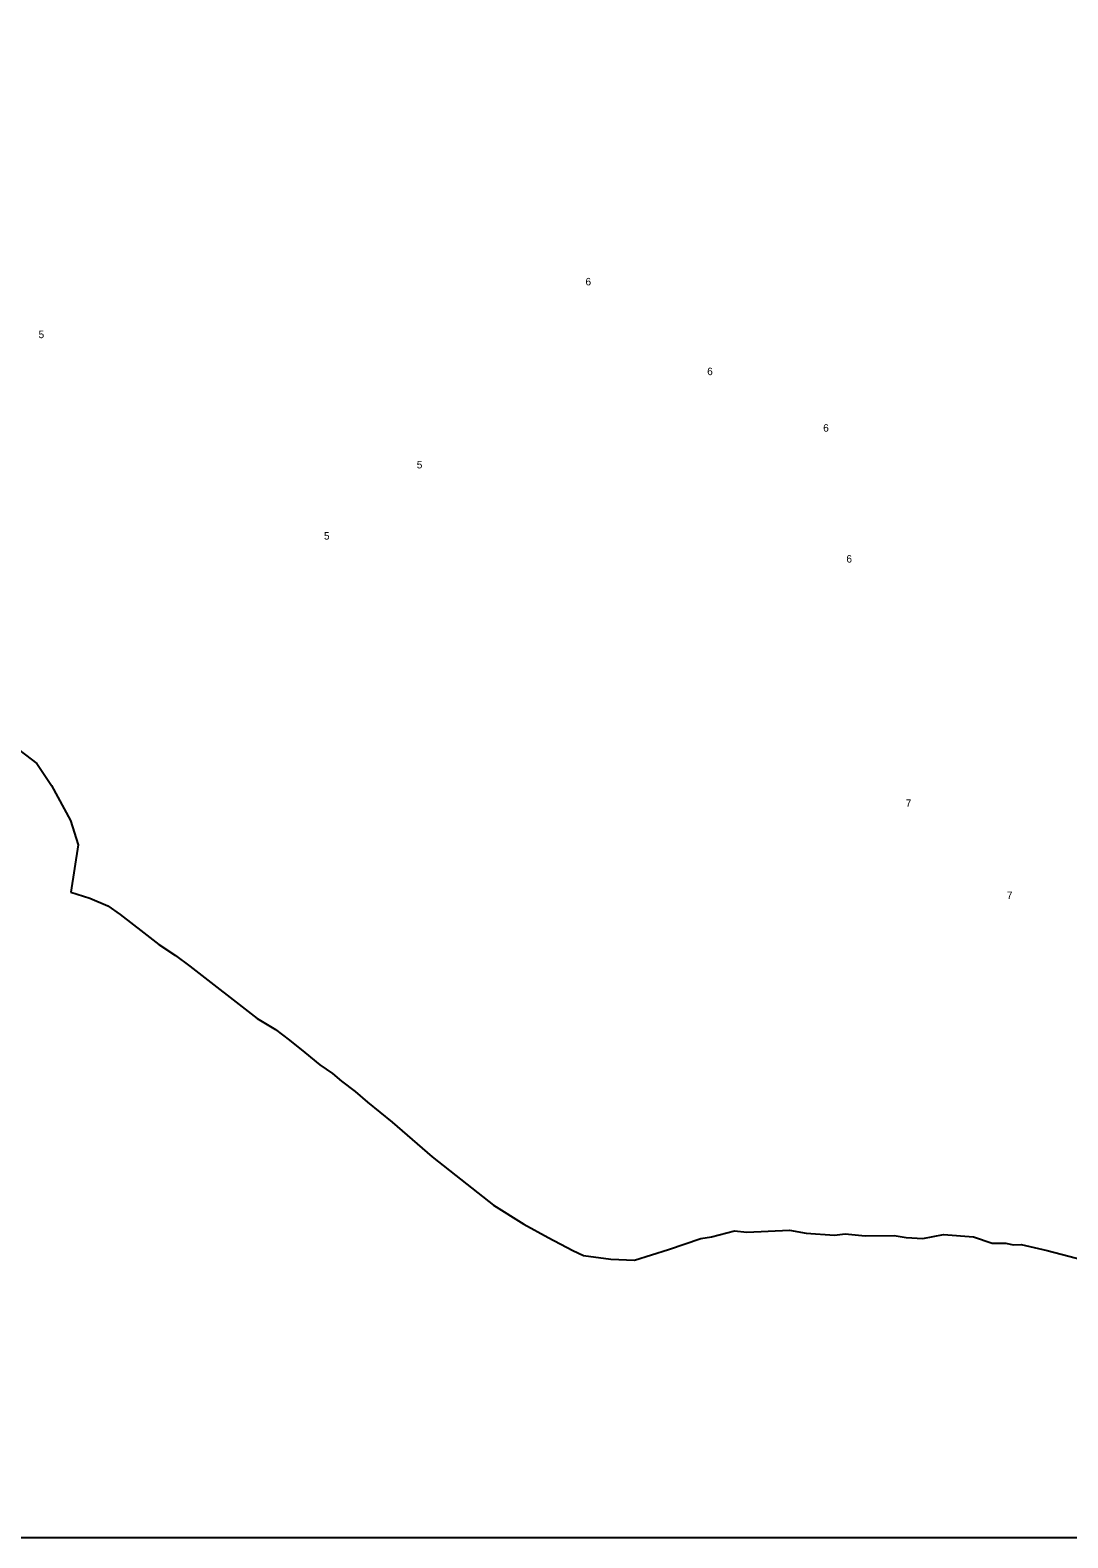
# Model space of a CAD drawing. Extents: x -780246 to -774760, y -968897 to -964868.
# Drawn here: x -777505 to -776119, y -968897 to -966883 of the extents above; entities that cross this region are included whole.
import ezdxf

# ---------------------------------------------------------------- set-up
doc = ezdxf.new("R2010")
doc.units = 0
doc.layers.add('Vrstva 13', color=7, linetype='Continuous')
doc.layers.add('Vrstva 15', color=7, linetype='Continuous')

msp = doc.modelspace()

# ---------------------------------------------------------------- linework, layer by layer
at = {"layer": 'Vrstva 13'}
for p, q in [((-777535.83, -967832.2), (-777496.1, -967862.6)), ((-777496.1, -967862.6), (-777476.3, -967891.68)), ((-777476.3, -967891.68), (-777451.02, -967938.67)), ((-777451.02, -967938.67), (-777440.87, -967971.05)), ((-777440.87, -967971.05), (-777450.66, -968034.26)), ((-777450.66, -968034.26), (-777425.38, -968042.15)), ((-777425.38, -968042.15), (-777401.2, -968052.67)), ((-777401.2, -968052.67), (-777384.62, -968064.29)), ((-777384.62, -968064.29), (-777353.28, -968088.7)), ((-777353.28, -968088.7), (-777332.98, -968104.41)), ((-777332.98, -968104.41), (-777311.02, -968119.1)), ((-777311.02, -968119.1), (-777291.7, -968133.2)), ((-777291.7, -968133.2), (-777201.62, -968203.22)), ((-777201.62, -968203.22), (-777177.3, -968218.05)), ((-777177.3, -968218.05), (-777158.59, -968232.08)), ((-777158.59, -968232.08), (-777138.06, -968248.53)), ((-777138.06, -968248.53), (-777117.83, -968265.19)), ((-777117.83, -968265.19), (-777101.16, -968276.8)), ((-777101.16, -968276.8), (-777089.11, -968286.67)), ((-777089.11, -968286.67), (-777070.7, -968300.7)), ((-777070.7, -968300.7), (-777054.26, -968314.73)), ((-777054.26, -968314.73), (-777021.25, -968341.77)), ((-777021.25, -968341.77), (-776967.91, -968387.82)), ((-776967.91, -968387.82), (-776921.67, -968424.28)), ((-776921.67, -968424.28), (-776885.8, -968452.42)), ((-776885.8, -968452.42), (-776845.62, -968478.07)), ((-776845.62, -968478.07), (-776812.75, -968495.61)), ((-776594.98, -968494.81), (-776564, -968486.91)), ((-776564, -968486.91), (-776547.61, -968488.56)), ((-776547.61, -968488.56), (-776490.73, -968485.9)), ((-776490.73, -968485.9), (-776468.23, -968489.77)), ((-776468.23, -968489.77), (-776430.46, -968492.62)), ((-776812.75, -968495.61), (-776779.95, -968513.08)), ((-776652.03, -968511.69), (-776609.22, -968496.93)), ((-776609.22, -968496.93), (-776594.98, -968494.81)), ((-776430.46, -968492.62), (-776416.14, -968490.79)), ((-776416.14, -968490.79), (-776389.54, -968493.65)), ((-776389.54, -968493.65), (-776350.89, -968493.13)), ((-776350.89, -968493.13), (-776334.6, -968495.84)), ((-776334.6, -968495.84), (-776312.42, -968497.22)), ((-776312.42, -968497.22), (-776284.88, -968491.7)), ((-776284.88, -968491.7), (-776244.78, -968494.7)), ((-776244.78, -968494.7), (-776219.68, -968503.43)), ((-776219.68, -968503.43), (-776201.53, -968503.28)), ((-776201.53, -968503.28), (-776191.55, -968505.72)), ((-776191.55, -968505.72), (-776181.2, -968505.2)), ((-776181.2, -968505.2), (-776146.15, -968513.26)), ((-776779.95, -968513.08), (-776765.93, -968519.8)), ((-776765.93, -968519.8), (-776729.46, -968524.84)), ((-776729.46, -968524.84), (-776697.83, -968526.16)), ((-776697.83, -968526.16), (-776652.03, -968511.69)), ((-776146.15, -968513.26), (-776088.5, -968528.4))]:
    msp.add_line(p, q, dxfattribs=at)
msp.add_lwpolyline([(-780246.31, -964867.52), (-774759.73, -964867.52), (-774759.73, -968897.03), (-780246.31, -968897.03)], close=True, dxfattribs=at)

# ---------------------------------------------------------------- texts
at = {"layer": 'Vrstva 15'}
for s, p in [('6', (-776763.08, -967223.63)), ('5', (-777493.756, -967294.14)), ('6', (-776600.5, -967343.56)), ('6', (-776445.53, -967419.03)), ('5', (-776988.476, -967468.18)), ('5', (-777112.466, -967563.25)), ('6', (-776414.53, -967593.96)), ('7', (-776335.266, -967920.41)), ('7', (-776200.176, -968043.55))]:
    msp.add_text(s, height=10, dxfattribs=at).set_placement(p)

doc.saveas('drawing.dxf')
